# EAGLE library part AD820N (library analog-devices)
Single-Supply, Rail-to-Rail, Low Power, FET Input Op Amp Source: http://www.analog.com/static/imported-files/data_sheets/AD820.pdf
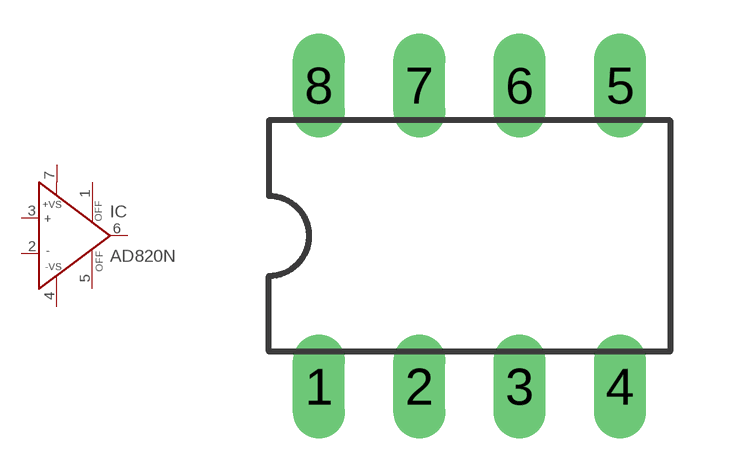
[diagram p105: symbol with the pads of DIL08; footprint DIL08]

Designator prefix IC

## AD820N (OC_FARNELL: 1438579; OC_NEWARK: unknown)  [DIL08]
1  OFF  pas
2  IN-  in
3  IN+  in
4  -VS  in
5  OFF  pas
6  OUT  out
7  +VS  in

## Footprint DIL08 (pad centres in mm)
Dual In Line Package
drill 0.813 long: 1 -3.81,-3.81; 2 -1.27,-3.81; 3 1.27,-3.81; 4 3.81,-3.81; 5 3.81,3.81; 6 1.27,3.81; 7 -1.27,3.81; 8 -3.81,3.81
